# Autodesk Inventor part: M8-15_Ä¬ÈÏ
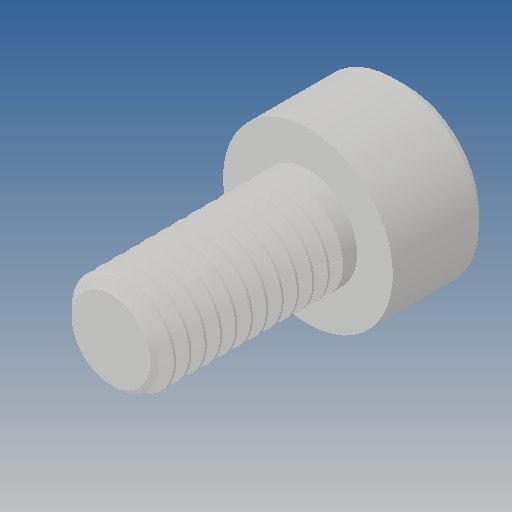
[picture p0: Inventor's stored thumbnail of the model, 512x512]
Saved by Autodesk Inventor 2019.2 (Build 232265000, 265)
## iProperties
Created: 2010-06
Part Number: M8-15_Ä¬ÈÏ
Material: Ogólny
Document SubType Name: Modeling
Designer: CADENGINEERING4
Density: 1 g/cm^3
Appearance: Domyślna
Author: CADENGINEERING4
Revision Number: ÈÎºÎ
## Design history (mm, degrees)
feature "NONE"
node "Bryła1"
